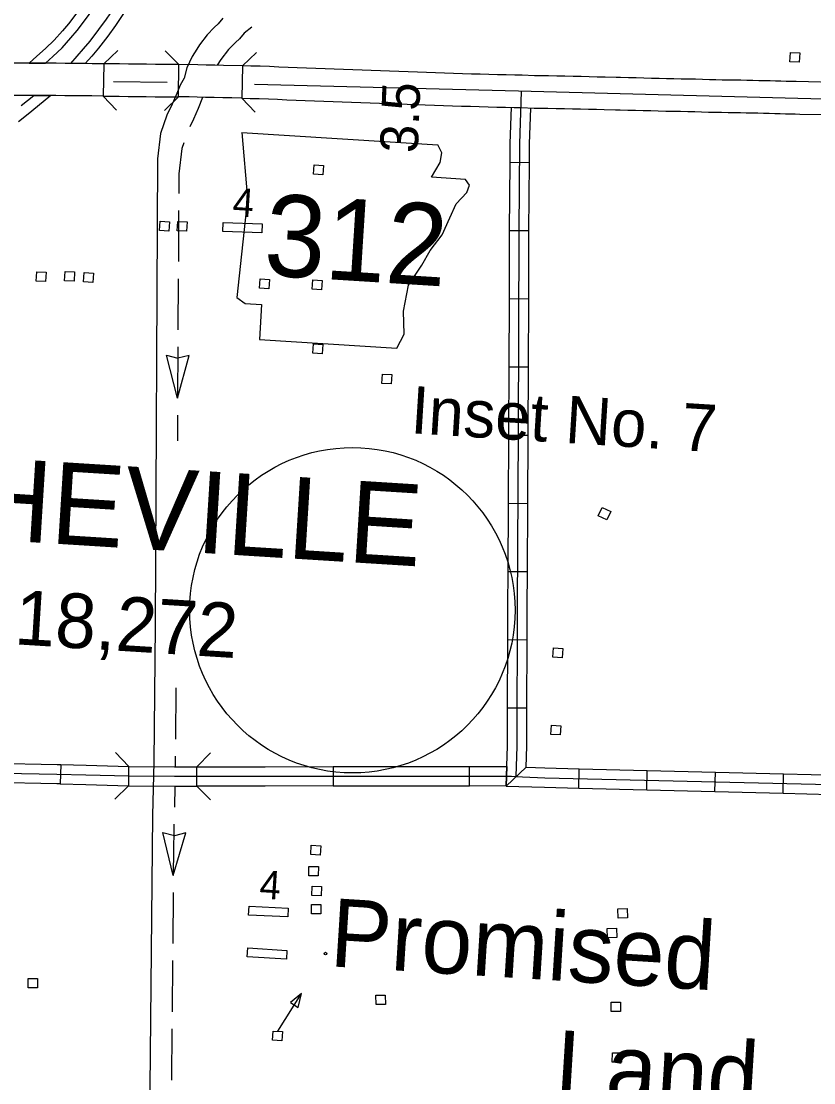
# Model space of a CAD drawing. Extents: x 1366406 to 1373462, y 376856 to 381998.
# Drawn here: x 1369334.8 to 1369434.3, y 379732.3 to 379865.5 of the extents above; entities that cross this region are included whole.
import ezdxf

# ---------------------------------------------------------------- set-up
doc = ezdxf.new("R2010")
doc.units = 0
for name, color, linetype in [('10', 7, 'Continuous'), ('19', 7, 'Continuous'), ('21', 7, 'Continuous'), ('24', 7, 'Continuous'), ('31', 7, 'Continuous'), ('32', 7, 'Continuous'), ('37', 7, 'Continuous'), ('38', 7, 'Continuous'), ('43', 7, 'Continuous'), ('48', 7, 'Continuous'), ('56', 7, 'Continuous'), ('6', 7, 'Continuous'), ('63', 7, 'Continuous')]:
    doc.layers.add(name, color=color, linetype=linetype)

msp = doc.modelspace()

# ---------------------------------------------------------------- linework, layer by layer
at = {"layer": '10'}
for points in [[(1369339.24, 379860.2), (1369338.11, 379860.21), (1369336.97, 379860.22), (1369335.81, 379860.23), (1369334.66, 379860.22), (1369333.51, 379860.23), (1369332.35, 379860.24), (1369331.18, 379860.25), (1369329.98, 379860.27), (1369328.2, 379860.29)], [(1369345.22, 379860.14), (1369343.74, 379860.15), (1369342.61, 379860.16), (1369341.48, 379860.17), (1369340.36, 379860.18), (1369339.24, 379860.2)], [(1369354.58, 379855.99), (1369354.61, 379860.04), (1369353.85, 379860.05), (1369352.77, 379860.05), (1369351.69, 379860.06), (1369350.58, 379860.07), (1369349.46, 379860.09), (1369348.32, 379860.1), (1369347.18, 379860.12), (1369346.03, 379860.14), (1369345.22, 379860.14), (1369345.13, 379856.09)], [(1369362.62, 379859.88), (1369360.24, 379859.93), (1369359.14, 379859.95), (1369358.07, 379859.97), (1369357.02, 379860), (1369354.61, 379860.04)], [(1369362.62, 379859.88), (1369362.52, 379855.83), (1369363.56, 379855.8), (1369364.71, 379855.77), (1369365.85, 379855.73), (1369367, 379855.68), (1369368.17, 379855.63), (1369369.34, 379855.59), (1369370.49, 379855.55), (1369371.65, 379855.5), (1369372.81, 379855.46), (1369373.97, 379855.42), (1369375.13, 379855.37), (1369376.29, 379855.33), (1369377.45, 379855.28), (1369378.61, 379855.24), (1369379.78, 379855.2), (1369380.94, 379855.16), (1369382.1, 379855.12), (1369383.25, 379855.09), (1369384.4, 379855.04), (1369385.54, 379855), (1369386.69, 379854.96), (1369387.83, 379854.92), (1369388.96, 379854.88), (1369390.08, 379854.84), (1369391.2, 379854.81), (1369392.31, 379854.77), (1369393.43, 379854.74), (1369394.53, 379854.71), (1369395.61, 379854.69), (1369396.68, 379854.67), (1369397.56, 379854.64), (1369399.2, 379854.59), (1369399.91, 379854.59), (1369400.91, 379854.57), (1369401.95, 379854.54), (1369402.99, 379854.52), (1369404.01, 379854.5), (1369405.01, 379854.48), (1369406.02, 379854.45), (1369407.02, 379854.43), (1369408, 379854.41), (1369409.4, 379854.36), (1369409.99, 379854.36), (1369410.95, 379854.34), (1369411.91, 379854.31), (1369412.87, 379854.28), (1369413.83, 379854.26), (1369414.78, 379854.24), (1369415.72, 379854.21), (1369416.65, 379854.19), (1369417.56, 379854.18), (1369418.47, 379854.16), (1369419.35, 379854.14), (1369420.21, 379854.12), (1369421.06, 379854.09), (1369421.9, 379854.07), (1369422.72, 379854.05), (1369423.53, 379854.04), (1369424.3, 379854.03), (1369425.07, 379854.02), (1369425.82, 379854), (1369426.55, 379853.99), (1369427.26, 379853.97), (1369427.98, 379853.95), (1369428.7, 379853.93), (1369429.41, 379853.91), (1369430.08, 379853.9), (1369430.73, 379853.88), (1369431.35, 379853.86), (1369431.95, 379853.85), (1369432.55, 379853.83), (1369438.23, 379853.74)], [(1369438.22, 379857.76), (1369432.06, 379857.9), (1369431.46, 379857.91), (1369430.83, 379857.93), (1369430.17, 379857.95), (1369429.5, 379857.96), (1369428.81, 379857.98), (1369428.11, 379858), (1369427.38, 379858.02), (1369426.63, 379858.04), (1369425.88, 379858.05), (1369425.13, 379858.07), (1369424.36, 379858.08), (1369423.58, 379858.09), (1369422.8, 379858.1), (1369422, 379858.12), (1369421.18, 379858.14), (1369420.32, 379858.17), (1369419.44, 379858.19), (1369418.55, 379858.21), (1369417.65, 379858.22), (1369416.73, 379858.24), (1369415.81, 379858.26), (1369414.88, 379858.28), (1369413.93, 379858.31), (1369412.98, 379858.33), (1369412.02, 379858.36), (1369411.05, 379858.39), (1369410.05, 379858.41), (1369409.48, 379858.41), (1369408.11, 379858.45), (1369407.11, 379858.48), (1369406.12, 379858.5), (1369405.11, 379858.53), (1369404.09, 379858.55), (1369403.07, 379858.57), (1369402.05, 379858.59), (1369401.02, 379858.62), (1369399.93, 379858.64), (1369399.25, 379858.64), (1369397.69, 379858.69), (1369396.78, 379858.72), (1369395.69, 379858.74), (1369394.61, 379858.76), (1369393.53, 379858.79), (1369392.44, 379858.82), (1369391.33, 379858.85), (1369390.22, 379858.89), (1369389.09, 379858.93), (1369387.96, 379858.97), (1369386.83, 379859.01), (1369385.7, 379859.05), (1369384.55, 379859.09), (1369383.39, 379859.13), (1369382.23, 379859.17), (1369381.07, 379859.21), (1369379.92, 379859.24), (1369378.77, 379859.29), (1369377.61, 379859.33), (1369376.45, 379859.38), (1369375.29, 379859.42), (1369374.12, 379859.47), (1369372.96, 379859.51), (1369371.81, 379859.55), (1369370.65, 379859.59), (1369369.48, 379859.64), (1369368.33, 379859.68), (1369367.18, 379859.73), (1369366.01, 379859.78), (1369364.84, 379859.82), (1369363.67, 379859.85), (1369362.62, 379859.88)], [(1369339.19, 379856.15), (1369338.06, 379856.16), (1369336.94, 379856.17), (1369335.81, 379856.18), (1369334.66, 379856.17), (1369333.49, 379856.18), (1369332.31, 379856.19), (1369331.12, 379856.2), (1369329.93, 379856.22), (1369328.16, 379856.24)], [(1369345.13, 379856.09), (1369343.71, 379856.1), (1369342.57, 379856.11), (1369341.45, 379856.12), (1369340.32, 379856.13), (1369339.19, 379856.15)], [(1369345.13, 379856.09), (1369345.98, 379856.09), (1369347.12, 379856.07), (1369348.27, 379856.05), (1369349.4, 379856.04), (1369350.53, 379856.03), (1369351.65, 379856.01), (1369352.74, 379856), (1369353.82, 379856), (1369354.58, 379855.99)], [(1369362.52, 379855.83), (1369361.27, 379855.85), (1369360.15, 379855.88), (1369359.05, 379855.9), (1369357.97, 379855.92), (1369356.92, 379855.96), (1369355.9, 379855.98), (1369354.58, 379855.99)]]:
    msp.add_lwpolyline(points, dxfattribs=at)
at = {"layer": '19'}
for points in [[(1369342.87, 379860.16), (1369341.06, 379860.18), (1369342.65, 379862), (1369343.48, 379862.98), (1369344.6, 379864.44), (1369345.55, 379865.73), (1369346.46, 379867.07), (1369347.32, 379868.45), (1369348.13, 379869.86), (1369348.89, 379871.29), (1369350.17, 379873.92), (1369351.05, 379876.12), (1369351.51, 379877.57), (1369351.9, 379878.94), (1369352.55, 379880.94), (1369352.84, 379882.19), (1369353.16, 379884.03), (1369353.31, 379885.65), (1369353.49, 379887.31), (1369353.65, 379890.55), (1369353.66, 379893.09), (1369353.55, 379895.04), (1369353.64, 379899.67)], [(1369337.9, 379860.21), (1369338.82, 379861.06), (1369339.98, 379862.15), (1369341.05, 379863.38), (1369341.85, 379864.3), (1369342.92, 379865.7), (1369343.83, 379866.95), (1369344.69, 379868.22), (1369345.51, 379869.53), (1369346.29, 379870.87), (1369347.01, 379872.25), (1369348.24, 379874.77), (1369349.07, 379876.83), (1369349.5, 379878.18), (1369349.89, 379879.56), (1369350.52, 379881.5), (1369350.77, 379882.6), (1369351.07, 379884.31), (1369351.22, 379885.86), (1369351.39, 379887.48), (1369351.54, 379890.61), (1369351.55, 379893.04), (1369351.45, 379894.98), (1369351.53, 379899.62)], [(1369355.01, 379899.53), (1369354.93, 379895.08), (1369355.04, 379893.12), (1369355.03, 379890.52), (1369354.86, 379887.2), (1369354.68, 379885.51), (1369354.52, 379883.84), (1369354.19, 379881.92), (1369353.88, 379880.57), (1369353.22, 379878.54), (1369352.83, 379877.18), (1369352.35, 379875.65), (1369351.43, 379873.36), (1369350.12, 379870.67), (1369349.34, 379869.19), (1369348.5, 379867.74), (1369347.61, 379866.32), (1369346.67, 379864.94), (1369345.7, 379863.61), (1369344.55, 379862.11), (1369343.69, 379861.1), (1369342.87, 379860.16)], [(1369341.81, 379866.53), (1369340.78, 379865.17), (1369340.01, 379864.28), (1369338.99, 379863.1), (1369337.89, 379862.07), (1369336.82, 379861.09), (1369335.84, 379860.23), (1369337.9, 379860.21)], [(1369334.85, 379854.89), (1369336.43, 379856.18), (1369338.58, 379856.16)], [(1369338.58, 379856.16), (1369336.9, 379854.79), (1369335.72, 379853.82)], [(1369335.71, 379853.82), (1369334.52, 379852.85)]]:
    msp.add_lwpolyline(points, dxfattribs=at)
at = {"layer": '21'}
for p, q in [((1369362.51, 379851.52), (1369363.23, 379843.24)), ((1369387.62, 379848.99), (1369387.11, 379849.97)), ((1369386.33, 379845.91), (1369387.4, 379847.76)), ((1369387.4, 379847.76), (1369387.62, 379848.99)), ((1369390.57, 379845.64), (1369386.33, 379845.91)), ((1369391.07, 379844.92), (1369390.57, 379845.64)), ((1369389.41, 379842.56), (1369390.74, 379843.98)), ((1369390.74, 379843.98), (1369391.07, 379844.92)), ((1369363.23, 379843.24), (1369361.9, 379830.83)), ((1369388.62, 379840.82), (1369389.41, 379842.56)), ((1369387.66, 379838.68), (1369388.62, 379840.82)), ((1369386.16, 379836.72), (1369387.66, 379838.68)), ((1369385.09, 379834.86), (1369386.16, 379836.72)), ((1369383.42, 379832.36), (1369385.09, 379834.86)), ((1369382.8, 379829.1), (1369383.42, 379832.36)), ((1369361.9, 379830.83), (1369362.95, 379830.07)), ((1369362.95, 379830.07), (1369365.01, 379829.94)), ((1369365.01, 379829.94), (1369364.73, 379825.57)), ((1369382.9, 379826.21), (1369382.8, 379829.1)), ((1369364.73, 379825.57), (1369381.96, 379824.49)), ((1369381.96, 379824.49), (1369382.9, 379826.21))]:
    msp.add_line(p, q, dxfattribs=at)
msp.add_lwpolyline([(1369362.51, 379851.52), (1369387.11, 379849.97)], dxfattribs=at)
at = {"layer": '31'}
for p, q in [((1369339.82, 379772.25), (1369339.75, 379769.82)), ((1369348.34, 379769.59), (1369348.34, 379772.02)), ((1369356.89, 379769.55), (1369356.89, 379771.98)), ((1369373.99, 379771.99), (1369373.99, 379769.56)), ((1369391.1, 379769.56), (1369391.1, 379771.99)), ((1369391.1, 379771.99), (1369391.1, 379771.99))]:
    msp.add_line(p, q, dxfattribs=at)
for points in [[(1369271.39, 379773.01), (1369284.28, 379772.55), (1369300.83, 379771.79), (1369314.18, 379771.61), (1369323.72, 379771.34), (1369339.33, 379771.05), (1369342.97, 379770.94), (1369348.33, 379770.81)], [(1369331.25, 379772.42), (1369339.36, 379772.27), (1369339.82, 379772.25)], [(1369339.82, 379772.25), (1369343.01, 379772.16), (1369348.35, 379772.02), (1369348.34, 379772.02)], [(1369348.34, 379772.02), (1369354.08, 379771.98), (1369356.89, 379771.98)], [(1369356.89, 379771.98), (1369365.44, 379771.98)], [(1369365.44, 379771.98), (1369373.99, 379771.99)], [(1369373.99, 379771.99), (1369382.55, 379771.99)], [(1369382.55, 379771.99), (1369391.1, 379771.99)], [(1369391.1, 379771.99), (1369395.77, 379771.99), (1369395.69, 379769.55)], [(1369348.33, 379770.81), (1369354.08, 379770.77), (1369396.34, 379770.77)], [(1369339.75, 379769.82), (1369339.3, 379769.84), (1369331.21, 379769.99)], [(1369339.75, 379769.82), (1369342.94, 379769.73), (1369348.31, 379769.59), (1369348.32, 379769.59)], [(1369348.32, 379769.59), (1369354.07, 379769.55), (1369356.89, 379769.55)], [(1369365.44, 379769.55), (1369356.89, 379769.55)], [(1369373.99, 379769.56), (1369365.44, 379769.55)], [(1369373.99, 379769.56), (1369382.55, 379769.56)], [(1369382.55, 379769.56), (1369391.1, 379769.56)], [(1369395.69, 379769.55), (1369391.1, 379769.56)]]:
    msp.add_lwpolyline(points, dxfattribs=at)
at = {"layer": '32'}
for p, q in [((1369398.61, 379847.73), (1369396.18, 379847.75)), ((1369398.55, 379839.18), (1369396.12, 379839.19)), ((1369398.52, 379830.63), (1369396.09, 379830.64)), ((1369398.49, 379822.08), (1369396.06, 379822.08)), ((1369398.46, 379813.52), (1369396.03, 379813.53)), ((1369398.4, 379804.96), (1369395.97, 379804.98)), ((1369398.35, 379796.41), (1369395.92, 379796.43)), ((1369398.31, 379787.86), (1369395.88, 379787.87)), ((1369398.3, 379779.31), (1369395.87, 379779.31)), ((1369398.2, 379771.9), (1369395.69, 379769.55)), ((1369404.79, 379769.28), (1369404.84, 379771.71)), ((1369413.34, 379769.07), (1369413.4, 379771.5)), ((1369421.89, 379768.86), (1369421.95, 379771.29)), ((1369430.44, 379768.65), (1369430.5, 379771.08))]:
    msp.add_line(p, q, dxfattribs=at)
for points in [[(1369396.94, 379770.76), (1369397.07, 379774.56), (1369397.1, 379792.13), (1369397.25, 379813.88), (1369397.34, 379839.19), (1369397.41, 379850.1), (1369397.62, 379856.67)], [(1369396.18, 379847.75), (1369396.19, 379850.13), (1369396.34, 379854.68)], [(1369398.61, 379847.73), (1369398.62, 379850.08), (1369398.77, 379854.58)], [(1369396.12, 379839.19), (1369396.12, 379839.19), (1369396.18, 379847.75)], [(1369398.55, 379839.18), (1369398.61, 379847.73)], [(1369396.09, 379830.64), (1369396.12, 379839.19)], [(1369398.52, 379830.63), (1369398.55, 379839.18)], [(1369396.06, 379822.08), (1369396.09, 379830.64)], [(1369398.49, 379822.08), (1369398.52, 379830.63)], [(1369396.03, 379813.53), (1369396.03, 379813.89), (1369396.06, 379822.08)], [(1369398.46, 379813.52), (1369398.46, 379813.87), (1369398.49, 379822.08)], [(1369395.97, 379804.98), (1369396.03, 379813.53)], [(1369398.4, 379804.96), (1369398.46, 379813.52)], [(1369395.92, 379796.43), (1369395.97, 379804.98)], [(1369398.35, 379796.41), (1369398.4, 379804.96)], [(1369395.88, 379787.87), (1369395.89, 379792.14), (1369395.92, 379796.43)], [(1369398.31, 379787.86), (1369398.32, 379792.12), (1369398.35, 379796.41)], [(1369395.87, 379779.31), (1369395.88, 379787.87)], [(1369398.3, 379779.31), (1369398.31, 379787.86)], [(1369395.69, 379769.55), (1369395.86, 379774.58), (1369395.87, 379779.31)], [(1369398.2, 379771.9), (1369398.29, 379774.54), (1369398.3, 379779.31)], [(1369398.2, 379771.9), (1369400.55, 379771.82), (1369404.84, 379771.71)], [(1369396.27, 379770.77), (1369396.96, 379770.76), (1369397.72, 379770.7), (1369400.52, 379770.6), (1369439.87, 379769.64), (1369439.93, 379767.85)], [(1369404.84, 379771.71), (1369413.4, 379771.5)], [(1369413.4, 379771.5), (1369421.95, 379771.29)], [(1369421.95, 379771.29), (1369430.5, 379771.08)], [(1369430.5, 379771.08), (1369437.42, 379770.91)], [(1369395.69, 379769.55), (1369400.48, 379769.39), (1369404.79, 379769.28)], [(1369404.79, 379769.28), (1369413.34, 379769.07)], [(1369413.34, 379769.07), (1369421.89, 379768.86)], [(1369421.89, 379768.86), (1369430.44, 379768.65)], [(1369430.44, 379768.65), (1369436.4, 379768.51)]]:
    msp.add_lwpolyline(points, dxfattribs=at)
at = {"layer": '37'}
for points in [[(1369345.22, 379860.14), (1369346.98, 379861.82)], [(1369352.91, 379861.77), (1369354.62, 379860.04)], [(1369362.62, 379859.88), (1369364.37, 379861.55)], [(1369346.81, 379854.34), (1369345.13, 379856.09)], [(1369354.58, 379855.99), (1369352.84, 379854.29)], [(1369364.2, 379854.07), (1369362.52, 379855.83)]]:
    msp.add_lwpolyline(points, dxfattribs=at)
at = {"layer": '38'}
for points in [[(1369346.67, 379773.77), (1369348.36, 379772.02)], [(1369356.89, 379771.98), (1369358.6, 379773.7)], [(1369348.32, 379769.59), (1369346.58, 379767.9)], [(1369358.6, 379767.84), (1369356.89, 379769.55)]]:
    msp.add_lwpolyline(points, dxfattribs=at)
at = {"layer": '43'}
for p, q in [((1369354.47, 379818.21), (1369353.06, 379823.59)), ((1369353.06, 379823.59), (1369354.48, 379823.2)), ((1369354.47, 379818.21), (1369355.93, 379823.57)), ((1369355.93, 379823.57), (1369354.5, 379823.2)), ((1369352.63, 379763.74), (1369354.06, 379763.35)), ((1369353.93, 379758.34), (1369352.63, 379763.74)), ((1369353.93, 379758.34), (1369355.51, 379763.67)), ((1369355.51, 379763.67), (1369354.08, 379763.3))]:
    msp.add_line(p, q, dxfattribs=at)
for points in [[(1369360.15, 379865.84), (1369359.55, 379865.13), (1369359.06, 379864.67), (1369358.16, 379863.79), (1369357.21, 379862.53), (1369356.86, 379861.97), (1369356.29, 379861.05), (1369355.63, 379859.65), (1369355.27, 379858.34), (1369354.78, 379857.45), (1369354.35, 379856.41), (1369353.78, 379855.07), (1369353.12, 379853.71), (1369352.3, 379851.4), (1369351.93, 379848.21), (1369351.63, 379789.62), (1369351.47, 379772.57), (1369351.3, 379765.85), (1369350.74, 379706.18)], [(1369363.77, 379864.72), (1369362.83, 379863.97), (1369362.24, 379863.27), (1369361.74, 379862.8), (1369361.45, 379862.51)], [(1369361.45, 379862.51), (1369360.84, 379861.92), (1369359.89, 379860.66), (1369359.44, 379859.95)], [(1369357.61, 379855.93), (1369357.03, 379854.54), (1369356.46, 379853.2), (1369355.99, 379852.22)], [(1369355.23, 379850.22), (1369354.99, 379849.53), (1369354.61, 379846.34), (1369354.6, 379843.87)], [(1369354.59, 379841.73), (1369354.56, 379835.32)], [(1369354.54, 379833.18), (1369354.51, 379826.76)], [(1369354.5, 379824.63), (1369354.47, 379818.21)], [(1369354.46, 379816.07), (1369354.44, 379812.86)], [(1369354.26, 379781.86), (1369354.2, 379775.44)], [(1369354.18, 379773.3), (1369354.17, 379771.98)], [(1369354.13, 379769.55), (1369354.06, 379766.89)], [(1369354.01, 379764.75), (1369353.99, 379763.99), (1369353.96, 379761.55)], [(1369353.96, 379761.55), (1369353.93, 379758.34)], [(1369353.91, 379756.2), (1369353.85, 379749.79)], [(1369353.83, 379747.65), (1369353.77, 379741.23)], [(1369353.75, 379739.09), (1369353.69, 379732.68)]]:
    msp.add_lwpolyline(points, dxfattribs=at)
at = {"layer": '56'}
for points in [[(1369431.28, 379860.4), (1369431.35, 379861.57), (1369432.53, 379861.5), (1369432.45, 379860.33)], [(1369371.51, 379846.28), (1369371.58, 379847.45), (1369372.76, 379847.37), (1369372.68, 379846.2)], [(1369352.21, 379839.24), (1369352.28, 379840.4), (1369353.45, 379840.33), (1369353.38, 379839.16)], [(1369354.41, 379839.2), (1369354.48, 379840.37), (1369355.66, 379840.3), (1369355.58, 379839.13)], [(1369360.13, 379839.11), (1369360.17, 379840.24), (1369365.09, 379840.06), (1369365.05, 379838.94)], [(1369336.72, 379832.89), (1369336.79, 379834.06), (1369337.96, 379833.99), (1369337.89, 379832.82)], [(1369340.29, 379832.93), (1369340.37, 379834.1), (1369341.54, 379834.03), (1369341.47, 379832.86)], [(1369342.66, 379832.77), (1369342.73, 379833.94), (1369343.91, 379833.87), (1369343.83, 379832.7)], [(1369364.75, 379832), (1369364.83, 379833.17), (1369366, 379833.1), (1369365.92, 379831.93)], [(1369371.35, 379831.87), (1369371.42, 379833.04), (1369372.6, 379832.96), (1369372.52, 379831.8)], [(1369371.45, 379823.85), (1369371.53, 379825.01), (1369372.7, 379824.94), (1369372.62, 379823.77)], [(1369380.1, 379820.05), (1369380.17, 379821.22), (1369381.34, 379821.15), (1369381.27, 379819.98)], [(1369407.24, 379803.45), (1369407.75, 379804.5), (1369408.81, 379803.99), (1369408.3, 379802.94)], [(1369401.56, 379785.72), (1369401.63, 379786.89), (1369402.8, 379786.82), (1369402.73, 379785.65)], [(1369401.3, 379776.03), (1369401.38, 379777.2), (1369402.55, 379777.12), (1369402.48, 379775.96)], [(1369371.17, 379760.95), (1369371.24, 379762.12), (1369372.42, 379762.05), (1369372.34, 379760.88)], [(1369370.94, 379758.3), (1369370.95, 379759.47), (1369372.13, 379759.46), (1369372.11, 379758.29)], [(1369371.29, 379755.83), (1369371.34, 379757), (1369372.51, 379756.95), (1369372.47, 379755.78)], [(1369371.27, 379753.54), (1369371.28, 379754.71), (1369372.45, 379754.7), (1369372.45, 379753.53)], [(1369363.38, 379753.37), (1369363.43, 379754.49), (1369368.35, 379754.25), (1369368.29, 379753.13)], [(1369409.73, 379752.96), (1369409.68, 379754.13), (1369410.85, 379754.19), (1369410.91, 379753.02)], [(1369408.39, 379750.52), (1369408.36, 379751.69), (1369409.54, 379751.72), (1369409.56, 379750.55)], [(1369363.21, 379748.13), (1369363.28, 379749.25), (1369368.19, 379748.94), (1369368.12, 379747.82)], [(1369335.73, 379744.24), (1369335.73, 379745.41), (1369336.9, 379745.41), (1369336.9, 379744.23)], [(1369368.62, 379742.39), (1369369.6, 379741.78), (1369370.03, 379743.54)], [(1369379.36, 379742.14), (1369379.35, 379743.31), (1369380.52, 379743.32), (1369380.54, 379742.15)], [(1369408.88, 379741.27), (1369408.86, 379742.45), (1369410.04, 379742.46), (1369410.05, 379741.29)], [(1369366.38, 379737.66), (1369366.45, 379738.82), (1369367.63, 379738.75), (1369367.55, 379737.58)], [(1369409, 379734.93), (1369409.01, 379736.1), (1369410.18, 379736.1), (1369410.18, 379734.93)]]:
    msp.add_lwpolyline(points, close=True, dxfattribs=at)
msp.add_lwpolyline([(1369367.04, 379738.79), (1369370.03, 379743.54)], dxfattribs=at)
msp.add_circle((1369373.02, 379748.53), 0.169, dxfattribs=at)
at = {"layer": '6'}
for points in [[(1369353.14, 379857.81), (1369346.43, 379857.89)], [(1369440.27, 379855.57), (1369397.25, 379856.69), (1369364.11, 379857.55)]]:
    msp.add_lwpolyline(points, dxfattribs=at)
at = {"layer": '63'}
msp.add_circle((1369376.4, 379791.6), 20.41, dxfattribs=at)

# ---------------------------------------------------------------- texts
at = {"layer": '21'}
msp.add_text('312', height=10.264, rotation=356.4139, dxfattribs=at).set_placement((1369365.14, 379833.63))
at = {"layer": '24'}
for s, p in [('Promised', (1369373.45, 379746.95)), ('Land', (1369401.68, 379730.42))]:
    msp.add_text(s, height=8.554, rotation=356.4139, dxfattribs=at).set_placement(p)
at = {"layer": '48'}
msp.add_text('3.5', height=4.752, rotation=87.8706, dxfattribs=at).set_placement((1369384.6, 379848.9))
at = {"layer": '56'}
for p in [(1369361.29, 379841.03), (1369364.66, 379755.45)]:
    msp.add_text('4', height=3.56, rotation=356.4139, dxfattribs=at).set_placement(p)
at = {"layer": '6'}
for s, height, p in [('BLYTHEVILLE', 10.2643, (1369294.21, 379802.76)), ('Pop. 18,272', 6.8429, (1369312.56, 379788.68))]:
    msp.add_text(s, height=height, rotation=356.4139, dxfattribs=at).set_placement(p)
at = {"layer": '63'}
msp.add_text('Inset No. 7', height=5.94, rotation=356.4139, dxfattribs=at).set_placement((1369383.6, 379813.81))

doc.saveas('drawing.dxf')
